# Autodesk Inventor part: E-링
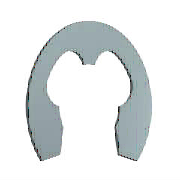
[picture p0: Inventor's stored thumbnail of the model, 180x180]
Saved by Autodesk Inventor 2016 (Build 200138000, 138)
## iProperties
IsCustomPart: 1
Created: 2012-02
Part Number: E-링
Material: 강철, 연강
Description: 리테이닝 링에 대한 사양- 탄소강 E 클립
Document SubType Name: Modeling
Standard: BS 3673-2
Designer: mduedu
Standards Organization: BSI
Language: ko-KR
Size Designation: 032MS
Categories: <MemberInstance><Categories><Category DisplayName="샤프트 부품" InternalName="7f7aeb1f-a693-4053-b835-cee3144e0d98" Mnemonic="SHFT"><Category DisplayName="써클립" Inter
Density: 1 g/cm^3
Appearance: 파란색 - 벽 페인트 - 광택
Author: mduedu
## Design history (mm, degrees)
sketch "스케치1"
  geometry: L1 (-0.4, 0.024)-(0, 0.024) reference; L2 (-3.206, 0)-(3.486, 0) reference; L3 (-1.833, -2.776)-(1.833, -2.776); L4 (0, 1.949)-(0, -3.479) reference; L5 (-2.4, -1.176)-(-2.008, -1.176); L6 (-0.4, 0.424)-(-0.4, 0.812); L7 (0, 1.524)-(2.53, 1.524); L8 (-1.833, -2.776)-(-2.096, -3.394); L9 (0, 0.024)-(-1.278, 0.024); L10 (1.833, -2.776)-(2.096, -3.394); L11 (2.4, -1.176)-(2.008, -1.176); L12 (0.4, 0.424)-(0.4, 0.812); C1 r 2 at (0, -1.976); A1 r 2 centre (0, -1.976) between (-1.894, -1.335) and (-1.833, -2.776); A2 r 0.4 centre (0, 0.424) between (-0.4, 0.424) and (0.4, 0.424); A3 r 3.5 centre (0, -1.976) between (3.196, -3.403) and (-3.196, -3.403); A4 r 3.2 centre (0, -1.976) between (-0.8, 1.122) and (-2.824, -0.47); A5 r 0.32 centre (-0.72, 0.812) between (-0.4, 0.812) and (-0.8, 1.122); A6 r 0.48 centre (-2.4, -0.696) between (-2.824, -0.47) and (-2.4, -1.176); A7 r 0.12 centre (-2.008, -1.296) between (-1.894, -1.335) and (-2.008, -1.176); A8 r 0.6 centre (-2.648, -3.158) between (-3.196, -3.403) and (-2.096, -3.394); A9 r 0.6 centre (2.648, -3.158) between (2.096, -3.394) and (3.196, -3.403); A10 r 2 centre (0, -1.976) between (1.833, -2.776) and (1.894, -1.335); A11 r 0.12 centre (2.008, -1.296) between (2.008, -1.176) and (1.894, -1.335); A12 r 0.48 centre (2.4, -0.696) between (2.4, -1.176) and (2.824, -0.47); A13 r 3.2 centre (0, -1.976) between (2.824, -0.47) and (0.8, 1.122); A14 r 0.32 centre (0.72, 0.812) between (0.8, 1.122) and (0.4, 0.812); 1 further point
  constraints: 30 point on circle, 20 end point, 15 centre point, 13 symmetric about line, 12 tangent, 8 point on line, 4 parallel, 2 coincident, 2 horizontal, 1 concentric, 1 perpendicular, 1 vertical alignment, 9 other
  dimensions: "d0" = 4 diameter of C1 (= WD); "d3" = 0.8 distance from line of A1.centre L3 (= 0.2 x ND); "d4" = 0.4 radius of A2 (= 0.1 x ND); "d5" = 7 diameter of A3 (= SD2); "d8" = 3.2 radius of A4 (= 0.8 x ND); "d9" = 0.8 distance from line of A1.centre L5 (= 0.2 x ND); "d10" = 0.32 radius of A5 (= 0.08 x ND); "d11" = 0.48 radius of A6 (= 0.12 x ND); "d12" = 0.12 radius of A7 (= 0.03 x ND); "d13" = 0.6 radius of A8 (= 0.15 x ND); "d14" = 2 distance from line of A1.centre L9 (= 0.5 x ND); "d15" = 2 radius of A1 (= 0.5 x ND)
extrude "본체" new body sketch "스케치1" distance "d16" = 0.62 (= SD); taper "d17" = 0 deg
workaxis "Work Axis1"
workaxis "Work Axis2"
workplane "Work Plane1"
body "Solid1"
other parameters: "ND" = 4 [user parameter; used in 14 equation terms], "SD" = 0.62 [user parameter; used in 1 equation term], "WD" = 4 (= WDMIN) [user parameter; used in 1 equation term], "d1" = 6.4 (= 1.6 x ND), "d2" = 4 (= ND), "SD2" = 7 [user parameter; used in 1 equation term], "d6" = 4 (= ND), "d7" = 0.6 (= 0.15 x ND), "d18" = 0, "d19" = 0, "d27" = 0, "d28" = 0, "WDMIN" = 4 [user parameter; used in 1 equation term], "SNB" = 0.67 [user parameter], "WDMAX" = 5 [user parameter], "BUBRMI" = 1 [user parameter]
